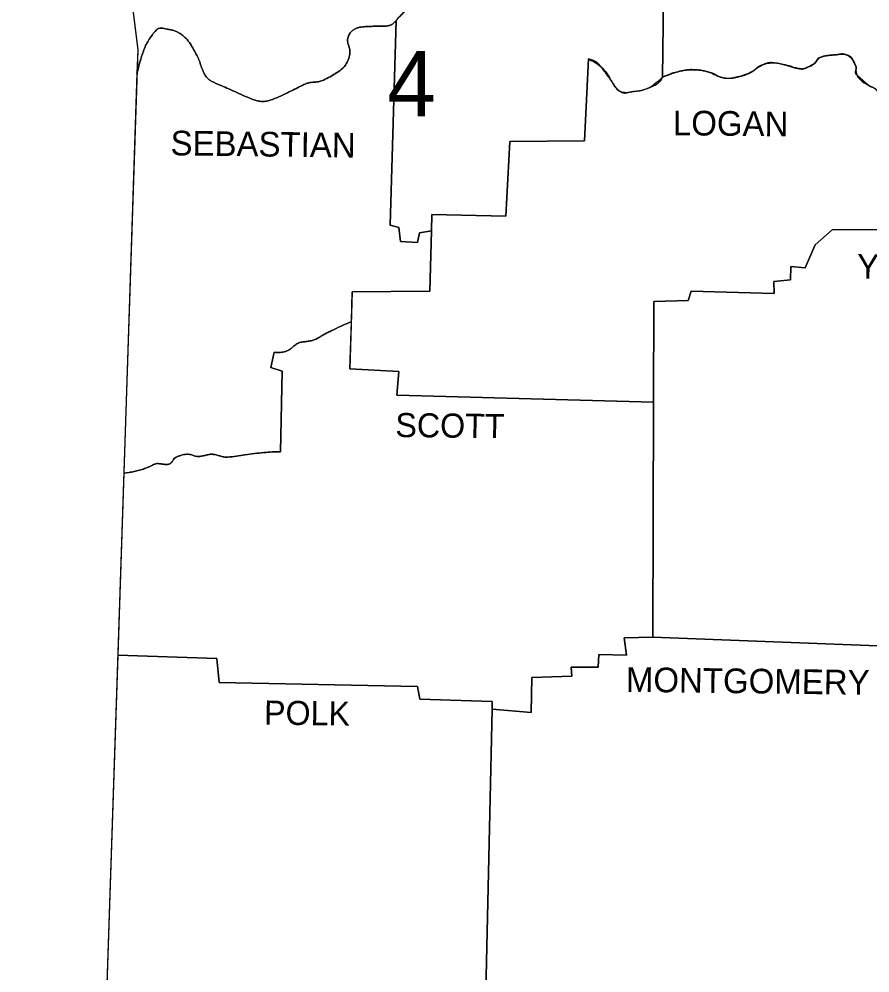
# Model space of a CAD drawing. Extents: x 185 to 5012, y 113 to 2127.
# Drawn here: x 2707 to 2852.2, y 1664.7 to 1827.4 of the extents above; entities that cross this region are included whole.
import ezdxf

# ---------------------------------------------------------------- set-up
doc = ezdxf.new("R2010")
doc.units = 0
doc.layers.add('Default', color=7, linetype='Continuous')
doc.layers.add('R_No Plot', color=7, linetype='Continuous')

msp = doc.modelspace()

# ---------------------------------------------------------------- linework, layer by layer
at = {"layer": 'Default'}
for points in [[(2707.02, 1984.77), (2727.28, 1822.16), (2718.47, 1556.71)], [(2817.48, 1873.91), (2816.8, 1817.46)], [(2771.34, 1827.12), (2770.33, 1792.22), (2771.79, 1791.82), (2772.09, 1789.48), (2775.02, 1789.28), (2775.32, 1790.94), (2777.38, 1791.29)], [(2804.18, 1820.59), (2803.49, 1806.6), (2790.77, 1806.5), (2790.09, 1793.78), (2777.47, 1794.07), (2777.08, 1780.96), (2763.87, 1780.87), (2763.48, 1767.75), (2771.79, 1767.27), (2771.5, 1763.25), (2815.27, 1762.04)], [(2868.46, 1805.62), (2868.07, 1791.53), (2845.76, 1791.43), (2842.83, 1788.89), (2841.16, 1784.97), (2838.72, 1785.17), (2838.62, 1782.92), (2835.78, 1782.63), (2835.88, 1780.57), (2821.69, 1780.96), (2821.2, 1779.4), (2815.33, 1779.2), (2815.27, 1762.04)], [(2751.64, 1753.57), (2751.93, 1767.36), (2749.97, 1767.95), (2750.56, 1770.59)], [(2815.27, 1762.04), (2815.14, 1721.96), (2810.24, 1721.87), (2810.64, 1718.93), (2805.94, 1719.03), (2805.84, 1716.88), (2801.24, 1716.88), (2801.34, 1715.31), (2794.49, 1715.11), (2794.39, 1709.15), (2787.74, 1709.73), (2786.66, 1661.59), (2749, 1661.69), (2748.12, 1650.54), (2749.49, 1649.56), (2749.39, 1637.04), (2721.18, 1638.28)], [(2853.49, 1720.5), (2815.14, 1721.96)], [(2723.85, 1718.93), (2740.78, 1718.34), (2741.17, 1714.23), (2775.02, 1713.55), (2775.41, 1711.4), (2787.74, 1711.01), (2787.74, 1709.73)]]:
    msp.add_lwpolyline(points, dxfattribs=at)
for points in [[(2777.96, 1845.25), (2778.04, 1844.73), (2778.08, 1844.21), (2777.96, 1843.19), (2777.78, 1842.65), (2777.57, 1842.12), (2777.36, 1841.58), (2777.17, 1841.04), (2776.68, 1839.18), (2776.69, 1838.57), (2776.84, 1837.96), (2776.98, 1837.34), (2777.01, 1837.04), (2776.98, 1836.73), (2776.62, 1835.73), (2776.1, 1834.78), (2775.8, 1834.37), (2775.45, 1833.99), (2775.11, 1833.62), (2774.83, 1833.21), (2774.74, 1832.75), (2774.83, 1832.23), (2774.92, 1831.72), (2774.83, 1831.25), (2774.67, 1830.98), (2774.51, 1830.71), (2774.16, 1830.18), (2773.78, 1829.67), (2773.36, 1829.2), (2771.79, 1827.63), (2771.17, 1826.93), (2770.83, 1826.61), (2770.64, 1826.47), (2770.53, 1826.41), (2770.42, 1826.36), (2769.82, 1826.2), (2769.21, 1826.16), (2768.59, 1826.17), (2768.28, 1826.18), (2767.98, 1826.17), (2766.95, 1826.12), (2765.92, 1826.07), (2765.39, 1826.02), (2764.87, 1825.91), (2764.37, 1825.71), (2764.12, 1825.56), (2763.87, 1825.38), (2763.54, 1825.06), (2763.32, 1824.7), (2763.17, 1824.32), (2763.08, 1823.92), (2763.11, 1823.36), (2763.27, 1822.79), (2763.44, 1822.23), (2763.48, 1821.67), (2763.39, 1821.11), (2763.24, 1820.56), (2762.69, 1819.51), (2761.73, 1818.56), (2760.64, 1817.85), (2759.54, 1817.25), (2758.39, 1816.77), (2757.81, 1816.65), (2757.2, 1816.6), (2756.61, 1816.54), (2756.04, 1816.38), (2755.23, 1816.01), (2754.42, 1815.61), (2753.62, 1815.21), (2752.81, 1814.82), (2749.88, 1813.55), (2749.11, 1813.36), (2748.31, 1813.35), (2747.5, 1813.49), (2746.75, 1813.74), (2743.81, 1815.01), (2741.17, 1816.19), (2740.62, 1816.42), (2740.07, 1816.66), (2739.56, 1816.96), (2739.33, 1817.14), (2739.22, 1817.25), (2739.11, 1817.36), (2738.56, 1818.21), (2738.17, 1819.13), (2737.84, 1820.07), (2737.66, 1820.53), (2737.45, 1820.98), (2736.93, 1821.97), (2736.37, 1822.94), (2736, 1823.49), (2735.57, 1824), (2735.08, 1824.46), (2734.81, 1824.68), (2734.52, 1824.89), (2733.97, 1825.2), (2733.41, 1825.42), (2732.84, 1825.56), (2732.27, 1825.68), (2731.79, 1825.77), (2731.3, 1825.82), (2730.82, 1825.75), (2730.61, 1825.65), (2730.5, 1825.57), (2730.41, 1825.48), (2729.09, 1823.73), (2728.23, 1821.92), (2727.65, 1820.05), (2727.14, 1818.14)], [(2804.18, 1820.59), (2806.33, 1819.22), (2807.99, 1816.97), (2809.46, 1815.11), (2811.91, 1815.01), (2813.86, 1815.4), (2816.8, 1817.46)], [(2816.8, 1817.46), (2820.03, 1818.54), (2822.38, 1818.73), (2824.72, 1818.34), (2827.17, 1817.36), (2829.81, 1817.56), (2831.77, 1818.24), (2833.73, 1819.51), (2835.88, 1819.9), (2837.93, 1819.51), (2840.09, 1818.93), (2842.43, 1819.61), (2843.8, 1820.88), (2846.15, 1821.27), (2848.21, 1821.27), (2849.67, 1819.61), (2849.97, 1817.85), (2851.83, 1816.19), (2853.49, 1815.11), (2853.98, 1813.06), (2854.86, 1811.59), (2855.74, 1810.61), (2857.01, 1810.02), (2859.16, 1810.22), (2862.49, 1809.53), (2864.64, 1809.04), (2866.6, 1807.38), (2868.46, 1805.62)], [(2750.56, 1770.59), (2751.09, 1770.52), (2751.64, 1770.53), (2752.46, 1770.7), (2752.59, 1770.74), (2752.71, 1770.79), (2752.99, 1770.92), (2753.25, 1771.09), (2753.74, 1771.48), (2754.23, 1771.87), (2754.63, 1772.1), (2754.77, 1772.16), (2755.1, 1772.26), (2755.44, 1772.32), (2756.15, 1772.42), (2756.85, 1772.53), (2757.19, 1772.62), (2757.51, 1772.74), (2758.2, 1773.1), (2758.87, 1773.49), (2759.55, 1773.86), (2760.25, 1774.21), (2763.72, 1775.8)], [(2751.64, 1753.57), (2750.93, 1753.58), (2750.22, 1753.57), (2748.8, 1753.47), (2745.57, 1753.08), (2742.64, 1752.69), (2742.3, 1752.68), (2741.97, 1752.71), (2741.31, 1752.88), (2740.65, 1753.07), (2740.16, 1753.16), (2739.99, 1753.18), (2739.38, 1753.12), (2738.77, 1752.99), (2738.16, 1752.85), (2737.55, 1752.78), (2737.13, 1752.85), (2736.72, 1752.98), (2736.3, 1753.11), (2735.89, 1753.18), (2735.37, 1753.15), (2734.86, 1753.05), (2734.34, 1752.89), (2733.83, 1752.69), (2733.49, 1752.43), (2733.23, 1752.08), (2732.98, 1751.74), (2732.66, 1751.51), (2732.37, 1751.45), (2732.06, 1751.44), (2731.43, 1751.51), (2730.81, 1751.58), (2730.35, 1751.55), (2730.21, 1751.51), (2729.77, 1751.33), (2729.34, 1751.11), (2728.9, 1750.9), (2728.45, 1750.73), (2727.56, 1750.47), (2726.67, 1750.24), (2725.78, 1750.07), (2724.88, 1749.93)]]:
    msp.add_spline(points, degree=3, dxfattribs=at)
at = {"layer": 'R_No Plot'}
for p, q in [((2816.8, 1817.46), (2817.48, 1873.91)), ((2817.48, 1873.91), (2816.8, 1817.46)), ((2771.34, 1827.12), (2771.24, 1827)), ((2771.79, 1827.63), (2771.34, 1827.12)), ((2835.79, 1819.91), (2835.88, 1819.9)), ((2727.14, 1818.14), (2724.88, 1749.98)), ((2826.82, 1817.45), (2827.17, 1817.36)), ((2849.97, 1817.85), (2851.59, 1816.37)), ((2777.47, 1794.07), (2777.38, 1791.29)), ((2838.72, 1785.17), (2838.62, 1782.92)), ((2838.62, 1782.92), (2835.78, 1782.63)), ((2821.69, 1780.96), (2821.2, 1779.4)), ((2821.2, 1779.4), (2815.33, 1779.2)), ((2815.33, 1779.2), (2815.27, 1762.04)), ((2815.27, 1762.04), (2815.14, 1721.96)), ((2724.88, 1749.93), (2723.85, 1718.93)), ((2815.14, 1721.96), (2853.49, 1720.5)), ((2853.49, 1720.5), (2815.14, 1721.96)), ((2723.85, 1718.93), (2721.18, 1638.28)), ((2805.94, 1719.03), (2805.84, 1716.88)), ((2810.64, 1718.93), (2805.94, 1719.03)), ((2794.49, 1715.11), (2794.39, 1709.15)), ((2801.34, 1715.31), (2794.49, 1715.11))]:
    msp.add_line(p, q, dxfattribs=at)
for points in [[(2720.83, 1873.93), (2727.28, 1822.16), (2727.14, 1818.14)], [(2771.34, 1827.12), (2770.33, 1792.22), (2771.79, 1791.82), (2772.09, 1789.48), (2775.02, 1789.28), (2775.32, 1790.94), (2777.38, 1791.29)], [(2777.38, 1791.29), (2775.32, 1790.94), (2775.02, 1789.28), (2772.09, 1789.48), (2771.79, 1791.82), (2770.33, 1792.22), (2771.34, 1827.12)], [(2777.38, 1791.29), (2777.47, 1794.07), (2790.09, 1793.78), (2790.77, 1806.5), (2803.49, 1806.6), (2804.18, 1820.59)], [(2804.18, 1820.59), (2803.49, 1806.6), (2790.77, 1806.5)], [(2790.77, 1806.5), (2790.09, 1793.78), (2777.47, 1794.07)], [(2815.27, 1762.04), (2815.33, 1779.2), (2821.2, 1779.4), (2821.69, 1780.96), (2835.88, 1780.57), (2835.78, 1782.63), (2838.62, 1782.92), (2838.72, 1785.17), (2841.16, 1784.97), (2842.83, 1788.89), (2845.76, 1791.43), (2868.07, 1791.53), (2868.46, 1805.62)], [(2868.46, 1805.62), (2868.07, 1791.53), (2845.76, 1791.43), (2842.83, 1788.89)], [(2777.38, 1791.29), (2777.08, 1780.96), (2763.87, 1780.87), (2763.48, 1767.75), (2771.79, 1767.27), (2771.5, 1763.25), (2815.27, 1762.04)], [(2763.72, 1775.8), (2763.87, 1780.87), (2777.08, 1780.96), (2777.38, 1791.29)], [(2842.83, 1788.89), (2841.16, 1784.97), (2838.72, 1785.17)], [(2835.78, 1782.63), (2835.88, 1780.57), (2821.69, 1780.96)], [(2815.27, 1762.04), (2771.5, 1763.25), (2771.79, 1767.27), (2763.48, 1767.75), (2763.72, 1775.8)], [(2751.64, 1753.57), (2751.93, 1767.36), (2749.97, 1767.95), (2750.56, 1770.59)], [(2750.56, 1770.59), (2749.97, 1767.95), (2751.93, 1767.36), (2751.64, 1753.57)], [(2787.74, 1709.73), (2794.39, 1709.15), (2794.49, 1715.11), (2801.34, 1715.31), (2801.24, 1716.88), (2805.84, 1716.88), (2805.94, 1719.03), (2810.64, 1718.93), (2810.24, 1721.87), (2815.14, 1721.96), (2815.27, 1762.04)], [(2815.14, 1721.96), (2810.24, 1721.87), (2810.64, 1718.93)], [(2787.74, 1709.73), (2787.74, 1711.01), (2775.41, 1711.4), (2775.02, 1713.55), (2741.17, 1714.23), (2740.78, 1718.34), (2723.85, 1718.93)], [(2723.85, 1718.93), (2740.78, 1718.34), (2741.17, 1714.23), (2775.02, 1713.55), (2775.41, 1711.4)], [(2805.84, 1716.88), (2801.24, 1716.88), (2801.34, 1715.31)], [(2775.41, 1711.4), (2787.74, 1711.01), (2787.74, 1709.73)], [(2721.18, 1638.28), (2749.39, 1637.04), (2749.49, 1649.56), (2748.12, 1650.54), (2749, 1661.69), (2786.66, 1661.59), (2787.74, 1709.73)], [(2794.39, 1709.15), (2787.74, 1709.73), (2786.66, 1661.59)]]:
    msp.add_lwpolyline(points, dxfattribs=at)
for points, degree in [([(2771.24, 1827), (2771.42, 1827.21), (2771.6, 1827.43), (2771.79, 1827.63), (2772.3, 1828.17), (2772.85, 1828.66), (2773.36, 1829.2), (2773.5, 1829.35), (2773.64, 1829.51), (2773.78, 1829.67), (2773.91, 1829.84), (2774.04, 1830), (2774.16, 1830.18), (2774.28, 1830.35), (2774.4, 1830.53), (2774.51, 1830.71), (2774.56, 1830.8), (2774.62, 1830.89), (2774.67, 1830.98), (2774.72, 1831.07), (2774.78, 1831.16), (2774.83, 1831.25), (2774.9, 1831.4), (2774.94, 1831.56), (2774.92, 1831.72), (2774.89, 1831.89), (2774.86, 1832.06), (2774.83, 1832.23), (2774.8, 1832.4), (2774.77, 1832.58), (2774.74, 1832.75), (2774.72, 1832.9), (2774.75, 1833.06), (2774.83, 1833.21), (2774.9, 1833.37), (2774.99, 1833.5), (2775.11, 1833.62), (2775.22, 1833.75), (2775.33, 1833.87), (2775.45, 1833.99), (2775.56, 1834.12), (2775.68, 1834.24), (2775.8, 1834.37), (2775.91, 1834.49), (2776, 1834.63), (2776.1, 1834.78), (2776.3, 1835.08), (2776.46, 1835.4), (2776.62, 1835.73), (2776.77, 1836.05), (2776.89, 1836.38), (2776.98, 1836.73), (2777, 1836.83), (2777.01, 1836.94), (2777.01, 1837.04), (2777.01, 1837.14), (2777.01, 1837.24), (2776.98, 1837.34), (2776.93, 1837.55), (2776.88, 1837.75), (2776.84, 1837.96), (2776.79, 1838.16), (2776.73, 1838.37), (2776.69, 1838.57), (2776.64, 1838.77), (2776.65, 1838.98), (2776.68, 1839.18), (2776.81, 1839.81), (2776.97, 1840.43), (2777.17, 1841.04), (2777.24, 1841.22), (2777.29, 1841.4), (2777.36, 1841.58), (2777.43, 1841.76), (2777.5, 1841.94), (2777.57, 1842.12), (2777.64, 1842.29), (2777.71, 1842.47), (2777.78, 1842.65), (2777.85, 1842.83), (2777.9, 1843), (2777.96, 1843.19), (2778.05, 1843.53), (2778.08, 1843.87), (2778.08, 1844.21), (2778.08, 1844.39), (2778.07, 1844.56), (2778.04, 1844.73), (2778.02, 1844.91), (2778, 1845.08), (2777.96, 1845.25)], 3), ([(2806.33, 1819.22), (2805.79, 1819.9), (2804.97, 1820.34), (2804.18, 1820.59)], 2), ([(2868.46, 1805.62), (2867.86, 1806.23), (2867.23, 1806.8), (2866.6, 1807.38), (2865.97, 1807.97), (2865.46, 1808.73), (2864.64, 1809.04), (2863.94, 1809.31), (2863.21, 1809.38), (2862.49, 1809.53), (2861.38, 1809.77), (2860.27, 1810), (2859.16, 1810.22), (2858.46, 1810.36), (2857.73, 1809.91), (2857.01, 1810.02), (2856.55, 1810.09), (2856.12, 1810.29), (2855.74, 1810.61), (2855.38, 1810.91), (2855.12, 1811.23), (2854.86, 1811.59), (2854.52, 1812.06), (2854.24, 1812.55), (2853.98, 1813.06), (2853.66, 1813.68), (2853.97, 1814.57), (2853.49, 1815.11), (2853.04, 1815.62), (2852.35, 1815.78), (2851.83, 1816.19), (2851.17, 1816.7), (2850.51, 1817.2), (2849.97, 1817.85), (2849.58, 1818.31), (2849.96, 1819.07), (2849.67, 1819.61), (2849.32, 1820.29), (2848.94, 1821.05), (2848.21, 1821.27), (2847.53, 1821.49), (2846.83, 1821.34), (2846.15, 1821.27), (2845.36, 1821.2), (2844.57, 1821.13), (2843.8, 1820.88), (2843.2, 1820.69), (2843.03, 1819.91), (2842.43, 1819.61), (2841.65, 1819.22), (2840.87, 1818.78), (2840.09, 1818.93), (2839.37, 1819.06), (2838.66, 1819.35), (2837.93, 1819.51), (2837.25, 1819.67), (2836.56, 1819.82), (2835.88, 1819.9), (2835.16, 1820), (2834.44, 1819.81), (2833.73, 1819.51), (2832.96, 1819.19), (2832.48, 1818.57), (2831.77, 1818.24), (2831.14, 1817.95), (2830.49, 1817.73), (2829.81, 1817.56), (2828.95, 1817.34), (2828.02, 1817.21), (2827.17, 1817.36), (2826.32, 1817.51), (2825.58, 1818.13), (2824.72, 1818.34), (2823.95, 1818.53), (2823.16, 1818.69), (2822.38, 1818.73), (2821.6, 1818.77), (2820.81, 1818.71), (2820.03, 1818.54), (2818.9, 1818.28), (2817.84, 1817.94), (2816.8, 1817.46)], 3), ([(2833.73, 1819.51), (2834.41, 1819.8), (2835.1, 1819.98), (2835.79, 1819.91)], 2), ([(2839.76, 1819), (2839.87, 1818.97), (2839.98, 1818.95), (2840.09, 1818.93), (2840.87, 1818.78), (2841.65, 1819.22), (2842.43, 1819.61), (2842.73, 1819.76), (2842.92, 1820.03), (2843.12, 1820.29)], 3), ([(2843.12, 1820.29), (2843.31, 1820.55), (2843.5, 1820.79), (2843.8, 1820.88), (2844.57, 1821.13), (2845.36, 1821.2), (2846.15, 1821.27), (2846.83, 1821.34), (2847.53, 1821.49), (2848.21, 1821.27)], 3), ([(2848.21, 1821.27), (2848.94, 1821.05), (2849.32, 1820.29), (2849.67, 1819.61)], 2), ([(2816.8, 1817.46), (2817.84, 1817.94), (2818.9, 1818.28), (2820.03, 1818.54), (2820.81, 1818.71), (2821.6, 1818.77), (2822.38, 1818.73), (2823.16, 1818.69), (2823.95, 1818.53), (2824.72, 1818.34), (2825.03, 1818.27), (2825.31, 1818.14), (2825.59, 1818.01)], 3), ([(2831.77, 1818.24), (2832.48, 1818.57), (2832.96, 1819.19), (2833.73, 1819.51)], 2), ([(2835.88, 1819.9), (2836.56, 1819.82), (2837.25, 1819.67), (2837.93, 1819.51), (2838.55, 1819.38), (2839.15, 1819.14), (2839.76, 1819)], 3), ([(2849.67, 1819.61), (2849.96, 1819.07), (2849.58, 1818.31), (2849.97, 1817.85)], 2), ([(2816.8, 1817.46), (2816.28, 1816.38), (2815.03, 1815.82), (2813.86, 1815.4), (2813.22, 1815.17), (2812.56, 1815.09), (2811.91, 1815.01), (2811.1, 1814.92), (2810.15, 1814.52), (2809.46, 1815.11)], 3), ([(2825.59, 1818.01), (2826, 1817.81), (2826.4, 1817.59), (2826.82, 1817.45)], 2), ([(2827.17, 1817.36), (2827.31, 1817.34), (2827.45, 1817.32), (2827.6, 1817.31)], 2), ([(2827.6, 1817.31), (2828.33, 1817.25), (2829.09, 1817.37), (2829.81, 1817.56)], 2), ([(2829.81, 1817.56), (2830.49, 1817.73), (2831.14, 1817.95), (2831.77, 1818.24)], 2), ([(2851.59, 1816.37), (2851.67, 1816.31), (2851.75, 1816.25), (2851.83, 1816.19)], 2), ([(2851.83, 1816.19), (2852.02, 1816.03), (2852.25, 1815.91), (2852.47, 1815.8)], 2)]:
    msp.add_open_spline(points, degree=degree, dxfattribs=at)
for points in [[(2757.13, 1816.6), (2757.2, 1816.6), (2757.81, 1816.65), (2758.39, 1816.77), (2759.54, 1817.25), (2760.64, 1817.85), (2761.73, 1818.56), (2762.69, 1819.51), (2763.24, 1820.56), (2763.39, 1821.11), (2763.48, 1821.67), (2763.44, 1822.23), (2763.27, 1822.79), (2763.11, 1823.36), (2763.08, 1823.92), (2763.17, 1824.32), (2763.32, 1824.7), (2763.54, 1825.06), (2763.87, 1825.38), (2764.12, 1825.56), (2764.37, 1825.71), (2764.87, 1825.91), (2765.39, 1826.02), (2765.92, 1826.07), (2766.95, 1826.12), (2767.98, 1826.17), (2768.28, 1826.18), (2768.59, 1826.17), (2769.21, 1826.16), (2769.82, 1826.2), (2770.42, 1826.36), (2770.53, 1826.41), (2770.64, 1826.47), (2770.83, 1826.61), (2771.17, 1826.93), (2771.24, 1827)], [(2771.24, 1827), (2771.17, 1826.93), (2770.83, 1826.61), (2770.64, 1826.47), (2770.53, 1826.41), (2770.42, 1826.36), (2769.82, 1826.2), (2769.21, 1826.16), (2768.59, 1826.17), (2768.28, 1826.18), (2767.98, 1826.17), (2766.95, 1826.12), (2765.92, 1826.07), (2765.39, 1826.02), (2764.87, 1825.91), (2764.37, 1825.71), (2764.12, 1825.56), (2763.87, 1825.38), (2763.54, 1825.06), (2763.32, 1824.7), (2763.17, 1824.32), (2763.08, 1823.92), (2763.11, 1823.36), (2763.27, 1822.79), (2763.44, 1822.23), (2763.48, 1821.67), (2763.39, 1821.11), (2763.24, 1820.56), (2762.69, 1819.51), (2761.73, 1818.56), (2760.64, 1817.85), (2759.54, 1817.25), (2758.39, 1816.77), (2757.81, 1816.65), (2757.2, 1816.6), (2757.13, 1816.6)], [(2727.14, 1818.14), (2727.65, 1820.05), (2728.23, 1821.92), (2729.09, 1823.73), (2730.41, 1825.48), (2730.5, 1825.57), (2730.61, 1825.65), (2730.82, 1825.75), (2731.3, 1825.82), (2731.79, 1825.77), (2732.27, 1825.68), (2732.84, 1825.56), (2733.41, 1825.42), (2733.97, 1825.2), (2734.52, 1824.89), (2734.81, 1824.68), (2735.08, 1824.46), (2735.57, 1824), (2736, 1823.49), (2736.37, 1822.94), (2736.93, 1821.97), (2737.45, 1820.98), (2737.66, 1820.53), (2737.84, 1820.07), (2738.17, 1819.13), (2738.56, 1818.21), (2738.6, 1818.13)], [(2738.6, 1818.13), (2738.56, 1818.21), (2738.17, 1819.13), (2737.84, 1820.07), (2737.66, 1820.53), (2737.45, 1820.98), (2736.93, 1821.97), (2736.37, 1822.94), (2736, 1823.49), (2735.57, 1824), (2735.08, 1824.46), (2734.81, 1824.68), (2734.52, 1824.89), (2733.97, 1825.2), (2733.41, 1825.42), (2732.84, 1825.56), (2732.27, 1825.68), (2731.79, 1825.77), (2731.3, 1825.82), (2730.82, 1825.75), (2730.61, 1825.65), (2730.5, 1825.57), (2730.41, 1825.48), (2729.09, 1823.73), (2728.23, 1821.92), (2727.65, 1820.05), (2727.14, 1818.14)], [(2804.18, 1820.59), (2806.33, 1819.22), (2807.99, 1816.97), (2809.46, 1815.11), (2811.91, 1815.01), (2813.86, 1815.4), (2816.8, 1817.46)], [(2807.99, 1816.97), (2807.58, 1817.53), (2807.17, 1818.1), (2806.76, 1818.66), (2806.33, 1819.22)], [(2738.6, 1818.13), (2739.11, 1817.36), (2739.22, 1817.25), (2739.33, 1817.14), (2739.56, 1816.96), (2740.07, 1816.66), (2740.62, 1816.42), (2741.17, 1816.19), (2743.81, 1815.01), (2746.75, 1813.74), (2747.5, 1813.49), (2748.31, 1813.35), (2749.11, 1813.36), (2749.88, 1813.55), (2752.81, 1814.82), (2753.62, 1815.21), (2754.42, 1815.61), (2755.23, 1816.01), (2756.04, 1816.38), (2756.61, 1816.54), (2757.13, 1816.6)], [(2757.13, 1816.6), (2756.61, 1816.54), (2756.04, 1816.38), (2755.23, 1816.01), (2754.42, 1815.61), (2753.62, 1815.21), (2752.81, 1814.82), (2749.88, 1813.55), (2749.11, 1813.36), (2748.31, 1813.35), (2747.5, 1813.49), (2746.75, 1813.74), (2743.81, 1815.01), (2741.17, 1816.19), (2740.62, 1816.42), (2740.07, 1816.66), (2739.56, 1816.96), (2739.33, 1817.14), (2739.22, 1817.25), (2739.11, 1817.36), (2738.6, 1818.13)], [(2809.46, 1815.11), (2809.02, 1815.56), (2808.66, 1816.02), (2808.33, 1816.49), (2807.99, 1816.97)], [(2750.56, 1770.59), (2751.09, 1770.52), (2751.64, 1770.53), (2752.46, 1770.7), (2752.59, 1770.74), (2752.71, 1770.79), (2752.99, 1770.92), (2753.25, 1771.09), (2753.74, 1771.48), (2754.23, 1771.87), (2754.63, 1772.1), (2754.77, 1772.16), (2755.1, 1772.26), (2755.44, 1772.32), (2756.15, 1772.42), (2756.85, 1772.53), (2757.19, 1772.62), (2757.51, 1772.74), (2758.2, 1773.1), (2758.87, 1773.49), (2759.55, 1773.86), (2760.25, 1774.21), (2763.72, 1775.8)], [(2763.72, 1775.8), (2760.25, 1774.21), (2759.55, 1773.86), (2758.87, 1773.49), (2758.2, 1773.1), (2757.51, 1772.74), (2757.19, 1772.62), (2756.85, 1772.53), (2756.15, 1772.42), (2755.44, 1772.32), (2755.1, 1772.26), (2754.77, 1772.16), (2754.63, 1772.1), (2754.23, 1771.87), (2753.74, 1771.48), (2753.25, 1771.09), (2752.99, 1770.92), (2752.71, 1770.79), (2752.59, 1770.74), (2752.46, 1770.7), (2751.64, 1770.53), (2751.09, 1770.52), (2750.56, 1770.59)], [(2737.88, 1752.8), (2738.16, 1752.85), (2738.77, 1752.99), (2739.38, 1753.12), (2739.99, 1753.18), (2740.16, 1753.16), (2740.65, 1753.07), (2741.31, 1752.88), (2741.97, 1752.71), (2742.3, 1752.68), (2742.64, 1752.69), (2745.57, 1753.08), (2748.8, 1753.47), (2750.22, 1753.57), (2750.93, 1753.58), (2751.64, 1753.57)], [(2751.64, 1753.57), (2750.93, 1753.58), (2750.22, 1753.57), (2748.8, 1753.47), (2745.57, 1753.08), (2742.64, 1752.69), (2742.3, 1752.68), (2741.97, 1752.71), (2741.31, 1752.88), (2740.65, 1753.07), (2740.16, 1753.16), (2739.99, 1753.18), (2739.38, 1753.12), (2738.77, 1752.99), (2738.16, 1752.85), (2737.88, 1752.8)], [(2724.88, 1749.98), (2725.78, 1750.07), (2726.67, 1750.24), (2727.56, 1750.47), (2728.45, 1750.73), (2728.9, 1750.9), (2729.34, 1751.11), (2729.77, 1751.33), (2730.21, 1751.51), (2730.35, 1751.55), (2730.81, 1751.58), (2731.43, 1751.51), (2732.06, 1751.44), (2732.37, 1751.45), (2732.66, 1751.51), (2732.98, 1751.74), (2733.23, 1752.08), (2733.49, 1752.43), (2733.83, 1752.69), (2734.34, 1752.89), (2734.86, 1753.05), (2735.37, 1753.15), (2735.89, 1753.18), (2736.3, 1753.11), (2736.72, 1752.98), (2737.13, 1752.85), (2737.55, 1752.78), (2737.88, 1752.8)], [(2737.88, 1752.8), (2737.55, 1752.78), (2737.13, 1752.85), (2736.72, 1752.98), (2736.3, 1753.11), (2735.89, 1753.18), (2735.37, 1753.15), (2734.86, 1753.05), (2734.34, 1752.89), (2733.83, 1752.69), (2733.49, 1752.43), (2733.23, 1752.08), (2732.98, 1751.74), (2732.66, 1751.51), (2732.37, 1751.45), (2732.06, 1751.44), (2731.43, 1751.51), (2730.81, 1751.58), (2730.35, 1751.55), (2730.21, 1751.51), (2729.77, 1751.33), (2729.34, 1751.11), (2728.9, 1750.9), (2728.45, 1750.73), (2727.56, 1750.47), (2726.67, 1750.24), (2725.78, 1750.07), (2724.88, 1749.93)]]:
    msp.add_spline(points, degree=3, dxfattribs=at)

# ---------------------------------------------------------------- texts
at = {"layer": 'Default'}
msp.add_text('4', height=11.15, dxfattribs=at).set_placement((2769.85, 1810.79))
for s, height, rotation, p in [('LOGAN', 4.208, 359.3969, (2818.56, 1807.58)), ('SEBASTIAN', 4.207, 359.2816, (2732.85, 1804.15)), ('YELL', 4.208, 359.1987, (2849.97, 1783.12)), ('SCOTT', 4.11, 359.4063, (2771.21, 1756.11)), ('MONTGOMERY', 4.208, 359.2944, (2810.54, 1712.67)), ('POLK', 4.109, 359.2152, (2748.8, 1707.09))]:
    msp.add_text(s, height=height, rotation=rotation, dxfattribs=at).set_placement(p)

doc.saveas('drawing.dxf')
